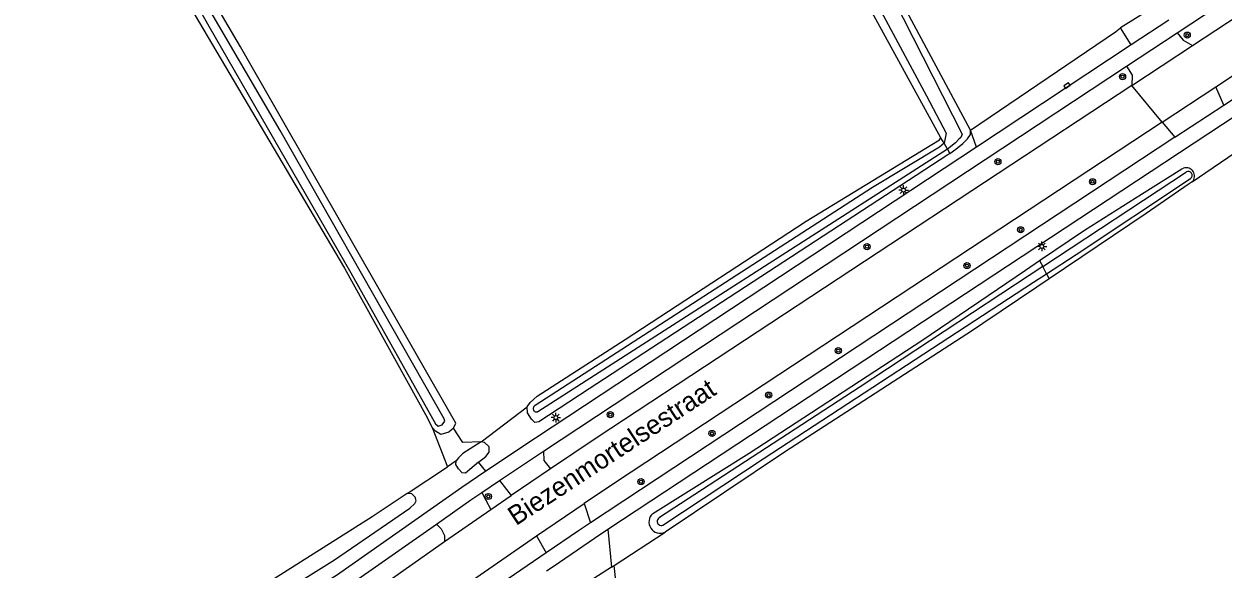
# Model space of a CAD drawing. Extents: x 140000 to 143000, y 403500 to 406000.
# Drawn here: x 140527 to 140683.1, y 404572.9 to 404643.8 of the extents above; entities that cross this region are included whole.
import ezdxf

# ---------------------------------------------------------------- set-up
doc = ezdxf.new("R2010")
doc.units = 0
for name, color, linetype in [('gg-afsc-erfafscheiding', 7, 'Continuous'), ('gg-anno-openbare ruimte label', 7, 'Continuous'), ('gg-knt-bronhoudergrens', 7, 'Continuous'), ('gg-knt-verharding', 7, 'Continuous'), ('gg-knt-verharding nz', 7, 'Continuous'), ('gg-kntw-bovenkant insteek waterloop', 7, 'Continuous'), ('gg-kntw-waterlijn', 7, 'Continuous'), ('gt-grn-groengrens', 7, 'Continuous'), ('gt-grn-vlakafsluiter', 7, 'Continuous'), ('gt-grn-weggrens', 7, 'Continuous'), ('gt-symb-boom', 7, 'Continuous'), ('gt-symb-kolk', 7, 'Continuous'), ('gt-symb-lichtmast', 7, 'Continuous')]:
    doc.layers.add(name, color=color, linetype=linetype)

# ---------------------------------------------------------------- blocks, each defined once
blk = doc.blocks.new('gt0-BOOM')
at = {"layer": 'gt-symb-boom'}
for radius in [0.4, 0.2]:
    blk.add_circle((0, 0), radius, dxfattribs=at)
blk = doc.blocks.new('gt0-KOLK')
at = {"layer": 'gt-symb-kolk'}
blk.add_lwpolyline([(0, 0), (0.38, 0), (0.38, 0.4), (-0.37, 0.4), (-0.37, 0), (0, 0)], dxfattribs=at)
blk = doc.blocks.new('gt0-LMAST')
at = {"layer": 'gt-symb-lichtmast'}
for p, q in [((-0.18, 0.17), (-0.45, 0.44)), ((-0.01, 0.25), (-0.01, 0.62)), ((0.17, 0.17), (0.44, 0.44)), ((-0.26, 0), (-0.63, 0)), ((-0.18, -0.18), (-0.45, -0.45)), ((-0.01, -0.25), (-0.01, -0.63)), ((0.44, -0.45), (0.17, -0.18)), ((0.24, 0), (0.62, 0))]:
    blk.add_line(p, q, dxfattribs=at)
blk.add_circle((-0.01, 0), 0.25, dxfattribs=at)

msp = doc.modelspace()

# ---------------------------------------------------------------- linework, layer by layer
at = {"layer": 'gg-afsc-erfafscheiding'}
msp.add_line((140603.43, 404573.14), (140603.75, 404573.35), dxfattribs=at)
msp.add_lwpolyline([(140650.12, 404629.98), (140668.96, 404642.78), (140669.6, 404643.32)], dxfattribs=at)
at = {"layer": 'gg-knt-bronhoudergrens'}
msp.add_lwpolyline([(140607.5, 404555.56), (140606.85, 404561.48), (140604.77, 404564.2), (140603.75, 404573.35)], dxfattribs=at)
at = {"layer": 'gg-knt-verharding'}
for p, q in [((140676.97, 404642.65), (140775.72, 404707.82)), ((140678.98, 404641), (140777.1, 404705.7)), ((140674.58, 404646.38), (140669.6, 404643.32)), ((140675.89, 404644.29), (140671.01, 404641.07)), ((140671.01, 404641.07), (140669.6, 404643.32)), ((140670.39, 404638.3), (140676.97, 404642.65)), ((140671.01, 404641.07), (140650.9, 404627.79)), ((140594.55, 404588.24), (140670.39, 404638.3)), ((140602.96, 404578.05), (140694.66, 404638.53)), ((140683.05, 404633.26), (140682, 404635.62)), ((140676.69, 404629.06), (140683.05, 404633.26)), ((140675.05, 404631.04), (140676.69, 404629.06)), ((140676.69, 404629.06), (140600.7, 404578.91)), ((140588.85, 404584.41), (140594.55, 404588.24)), ((140586.56, 404582.86), (140588.85, 404584.41)), ((140588.85, 404584.41), (140590.37, 404582.44)), ((140587.73, 404580.63), (140590.37, 404582.44)), ((140599.88, 404581.43), (140600.7, 404578.91)), ((140602.96, 404578.05), (140603.43, 404573.14)), ((140593.64, 404577.19), (140594.93, 404574.99)), ((140603.43, 404573.14), (140596.75, 404568.87))]:
    msp.add_line(p, q, dxfattribs=at)
for points in [[(140676.97, 404642.65), (140677.75, 404641.71), (140678.98, 404641)], [(140682, 404635.62), (140692.11, 404642.29), (140692.39, 404642.47)], [(140683.05, 404633.26), (140693.09, 404639.89), (140693.78, 404640.34)], [(140670.39, 404638.3), (140671.12, 404637.13), (140671.08, 404635.8)], [(140671.08, 404635.8), (140601.57, 404589.98), (140595.5, 404585.92)], [(140675.05, 404631.04), (140604.08, 404584.25), (140599.88, 404581.43)], [(140650.9, 404627.79), (140593.52, 404589.92), (140587.08, 404585.6)], [(140594.55, 404588.24), (140594.61, 404587.01), (140595.5, 404585.92)], [(140587.08, 404585.6), (140583.96, 404583.5), (140567.64, 404572.03), (140550.32, 404561.38), (140538.88, 404552.82), (140530.73, 404545.42)], [(140580.64, 404578.74), (140585.1, 404581.88), (140586.56, 404582.86)], [(140586.56, 404582.86), (140587.06, 404581.83), (140587.73, 404580.63)], [(140551.07, 404559.51), (140551.34, 404559.71), (140568.7, 404570.33), (140580.64, 404578.74)], [(140580.64, 404578.74), (140581.25, 404578.11), (140581.71, 404577.25), (140581.71, 404576.46)], [(140600.7, 404578.91), (140599.11, 404577.86), (140594.93, 404574.99)], [(140594.95, 404572.63), (140595.82, 404573.23), (140600.5, 404576.43), (140601.19, 404576.89), (140602.96, 404578.05)], [(140568.79, 404567.28), (140575.23, 404571.9), (140581.71, 404576.46)], [(140573.51, 404563.07), (140583.53, 404570.19), (140593.64, 404577.19)], [(140594.93, 404574.99), (140587.49, 404569.9), (140576.09, 404561.83), (140560.32, 404549.2)]]:
    msp.add_lwpolyline(points, dxfattribs=at)
at = {"layer": 'gg-knt-verharding nz'}
for p, q in [((140671.08, 404635.8), (140678.98, 404641)), ((140675.05, 404631.04), (140682, 404635.62)), ((140595.5, 404585.92), (140590.37, 404582.44)), ((140593.64, 404577.19), (140599.88, 404581.43)), ((140581.71, 404576.46), (140587.73, 404580.63))]:
    msp.add_line(p, q, dxfattribs=at)
at = {"layer": 'gg-kntw-bovenkant insteek waterloop'}
for p, q in [((140646.67, 404628.3), (140646.27, 404629.01)), ((140647.11, 404627.5), (140647.41, 404626.97)), ((140659.08, 404613.02), (140659.5, 404612.23)), ((140659.99, 404611.29), (140660.34, 404610.64))]:
    msp.add_line(p, q, dxfattribs=at)
for points in [[(140582.85, 404591.2), (140583.18, 404591.88), (140555.16, 404640.82), (140541.83, 404663.57), (140516.65, 404708.7), (140496.57, 404744.33), (140474.76, 404782.38), (140470.72, 404789.58)], [(140523.99, 404689.84), (140530.7, 404678.14), (140549.15, 404645.12), (140568.67, 404612.05), (140579.23, 404592.98), (140580.11, 404591.3)], [(140646.27, 404629.01), (140626.15, 404665.79), (140625.16, 404667.55)], [(140650.12, 404629.98), (140631.66, 404664.48), (140629.71, 404667.93)], [(140647.41, 404626.97), (140648.2, 404627.52), (140649.13, 404628.25), (140649.71, 404628.88), (140650.1, 404629.43), (140650.12, 404629.98)], [(140592.46, 404593.99), (140592.82, 404594.57), (140593.74, 404595.37), (140605.19, 404602.77), (140628.74, 404618.13), (140646.06, 404628.72), (140646.27, 404629.01)], [(140647.41, 404626.97), (140647.14, 404626.79), (140600.49, 404596.33), (140593.96, 404592.03), (140593.45, 404591.95), (140592.99, 404592.38), (140592.48, 404593.22), (140592.46, 404593.99)], [(140659.08, 404613.02), (140664.93, 404616.98), (140672.35, 404621.66), (140677.61, 404624.94), (140677.83, 404625.04)], [(140678.93, 404623.28), (140678.42, 404622.93), (140672.95, 404619.15), (140660.34, 404610.64)], [(140608.8, 404580.12), (140621.34, 404587.95), (140643.78, 404602.63), (140657.27, 404611.78), (140659.08, 404613.02)], [(140660.34, 404610.64), (140658.72, 404609.55), (140651.71, 404604.82), (140650.36, 404603.94)], [(140650.36, 404603.94), (140625.93, 404588.09), (140610.39, 404577.68)], [(140582.85, 404591.2), (140582.26, 404590.7), (140581.23, 404590.38), (140580.54, 404590.83), (140580.11, 404591.3)], [(140586.48, 404589.42), (140584.08, 404587.9), (140583.5, 404587.34), (140583.19, 404586.95)], [(140586.12, 404586.77), (140587.05, 404587.53), (140587.51, 404588.09), (140587.49, 404588.79), (140586.9, 404589.34), (140586.48, 404589.42)], [(140586.12, 404586.77), (140584.43, 404585.37), (140583.98, 404585.42), (140583.52, 404585.91), (140583.18, 404586.47), (140583.19, 404586.95)], [(140576.82, 404582.69), (140572.28, 404579.67), (140556.59, 404569.76), (140534.87, 404555.04), (140528.38, 404550.52)], [(140528.83, 404547.51), (140538.75, 404555.11), (140544.14, 404559.18), (140548.33, 404562.29), (140553.66, 404565.49), (140567.39, 404574.09), (140577.17, 404580.82), (140577.82, 404581.39), (140578.03, 404581.74), (140577.89, 404582.25), (140577.46, 404582.65), (140576.82, 404582.69)]]:
    msp.add_lwpolyline(points, dxfattribs=at)
for centre, radius, start, end in [((140678.17, 404624.02), 1.07, 315.5784, 108.6076), ((140609.76, 404579.01), 1.47, 131.0513, 295.1085)]:
    msp.add_arc(centre, radius, start, end, dxfattribs=at)
at = {"layer": 'gg-kntw-waterlijn'}
for p, q in [((140647.11, 404627.5), (140593.83, 404593.34)), ((140659.5, 404612.23), (140678.19, 404624.57))]:
    msp.add_line(p, q, dxfattribs=at)
for points in [[(140524.58, 404692.94), (140499.06, 404737.76), (140478.92, 404773.45), (140470.33, 404788.9), (140469.6, 404789.77), (140469.25, 404789.72), (140468.79, 404789.29), (140469, 404788.6), (140482.63, 404763.59), (140496.59, 404739.14), (140512.48, 404711.54), (140531.42, 404678.32), (140551.05, 404643.54), (140569.51, 404611.44), (140580.54, 404591.76), (140580.87, 404591.45), (140581.37, 404591.66), (140581.74, 404592.11), (140581.66, 404592.43), (140560.34, 404629.96), (140549.79, 404648.04), (140524.58, 404692.94)], [(140626.11, 404668.08), (140630.75, 404659.9), (140644.39, 404634.45), (140646.95, 404629.61), (140646.67, 404628.3)], [(140629.1, 404668.02), (140634.98, 404657.12), (140649.02, 404629.46), (140648.85, 404629.05), (140648.6, 404628.8), (140648.14, 404628.35), (140647.11, 404627.5)], [(140646.67, 404628.3), (140646.06, 404627.78), (140637.37, 404622.54), (140593.5, 404594.15)], [(140659.99, 404611.29), (140663.86, 404613.82), (140678.73, 404623.7)], [(140659.5, 404612.23), (140657.73, 404611.07), (140635.64, 404596.49), (140609.68, 404579.58)], [(140610.08, 404578.61), (140623.15, 404587.21), (140658.3, 404610.19), (140659.99, 404611.29)]]:
    msp.add_lwpolyline(points, dxfattribs=at)
for centre, radius, start, end in [((140678.41, 404624.1), 0.519, 308.9623, 115.0249), ((140593.66, 404593.75), 0.437, 112.162, 292.8762), ((140609.88, 404579.09), 0.528, 111.6126, 292.6346)]:
    msp.add_arc(centre, radius, start, end, dxfattribs=at)
at = {"layer": 'gt-grn-groengrens'}
for p, q in [((140678.93, 404623.28), (140685.37, 404627.63)), ((140586.48, 404589.42), (140592.46, 404593.99)), ((140580.11, 404591.3), (140582.07, 404586.2)), ((140576.82, 404582.69), (140582.07, 404586.2)), ((140583.19, 404586.95), (140582.07, 404586.2)), ((140603.75, 404573.35), (140610.39, 404577.68))]:
    msp.add_line(p, q, dxfattribs=at)
msp.add_lwpolyline([(140586.48, 404589.42), (140584.06, 404589.34), (140582.85, 404591.2)], dxfattribs=at)
at = {"layer": 'gt-grn-vlakafsluiter'}
for p, q in [((140647.11, 404627.5), (140646.67, 404628.3)), ((140659.99, 404611.29), (140659.5, 404612.23))]:
    msp.add_line(p, q, dxfattribs=at)
at = {"layer": 'gt-grn-weggrens'}
for p, q in [((140675.05, 404631.04), (140671.08, 404635.8)), ((140650.9, 404627.79), (140650.12, 404629.98)), ((140587.08, 404585.6), (140586.12, 404586.77))]:
    msp.add_line(p, q, dxfattribs=at)

# ---------------------------------------------------------------- block references
at = {"layer": 'gt-symb-boom'}
for p in [(140678.3, 404642.35), (140669.88, 404636.95), (140653.67, 404625.89), (140665.98, 404623.27), (140656.64, 404617.02), (140636.65, 404614.82), (140649.65, 404612.37), (140632.91, 404601.29), (140623.86, 404595.51), (140603.26, 404592.97), (140616.49, 404590.52), (140607.26, 404584.26), (140587.39, 404582.32)]:
    msp.add_blockref('gt0-BOOM', p, dxfattribs=at)
at = {"layer": 'gt-symb-kolk', "rotation": 33.423733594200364}
msp.add_blockref('gt0-KOLK', (140662.77, 404635.62), dxfattribs=at)
at = {"layer": 'gt-symb-lichtmast'}
for p in [(140641.41, 404622.19), (140659.4, 404614.86), (140596.18, 404592.59)]:
    msp.add_blockref('gt0-LMAST', p, dxfattribs=at)

# ---------------------------------------------------------------- texts
at = {"layer": 'gg-anno-openbare ruimte label'}
msp.add_text('Biezenmortelsestraat', height=2.5, rotation=33.3, dxfattribs=at).set_placement((140590.99, 404578.46))

doc.saveas('drawing.dxf')
